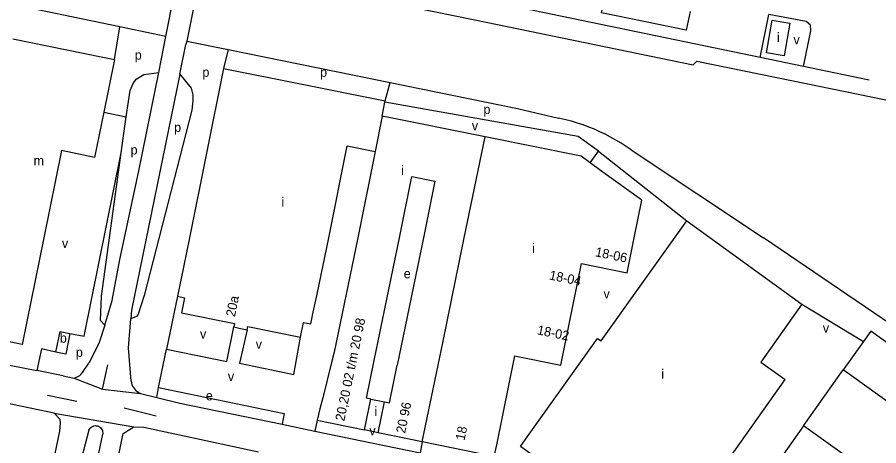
# Model space of a CAD drawing. Extents: x 157699 to 159683, y 381451 to 383293.
# Drawn here: x 158601.6 to 158968.6, y 382661.5 to 382844 of the extents above; entities that cross this region are included whole.
import ezdxf

# ---------------------------------------------------------------- set-up
doc = ezdxf.new("R2010")
doc.units = 0
for name, color, linetype in [('BLT_Basislijn', 7, 'Continuous'), ('BLT_Bebouwing', 7, 'Continuous'), ('BLT_Centroide', 7, 'Continuous'), ('BLT_Huisnummer', 7, 'Continuous'), ('BLT_Huisnummer_reeks', 7, 'Continuous'), ('BLT_Onderdoorgang_en_onderverdeling', 7, 'Continuous'), ('BLT_Onderverdeling_panden', 7, 'Continuous'), ('BLT_Vlakafsluiter', 7, 'Continuous')]:
    doc.layers.add(name, color=color, linetype=linetype)

msp = doc.modelspace()

# ---------------------------------------------------------------- linework, layer by layer
at = {"layer": 'BLT_Basislijn'}
for p, q in [((158645.35, 382839.82), (158432.83, 382884.22)), ((158664.82, 382835.75), (158669.66, 382859.56)), ((158678.92, 382859.01), (158673.76, 382833.82)), ((158918.11, 382826.83), (158801.5, 382851)), ((158918.11, 382826.83), (158921.71, 382845.17)), ((158642.99, 382826.01), (158645.35, 382839.82)), ((158664.82, 382835.75), (158645.35, 382839.82)), ((158661.89, 382820.42), (158664.82, 382835.75)), ((158670.79, 382819.7), (158673.45, 382832.31)), ((158673.76, 382833.82), (158673.45, 382832.31)), ((158673.76, 382833.82), (158691.37, 382830.23)), ((158691.37, 382830.23), (158689.49, 382822.2)), ((158691.37, 382830.23), (158760.4, 382816.15)), ((158936.46, 382823.03), (158918.11, 382826.83)), ((158964.55, 382817.2), (158936.46, 382823.03)), ((158931.34, 382817), (159045.89, 382793.42)), ((158758.28, 382808.34), (158760.4, 382816.15)), ((158760.4, 382816.15), (158814.72, 382805.07)), ((158638.43, 382803.49), (158648.01, 382801.54)), ((158814.72, 382805.07), (158832.18, 382801.03)), ((158863.07, 382787.52), (158919.5, 382750)), ((158845.69, 382781.94), (158849.21, 382786.88)), ((158849.21, 382786.88), (158886.76, 382757.21)), ((159006.18, 382690.97), (158919.5, 382750)), ((158669.87, 382725.15), (158665.12, 382702.55)), ((158935.87, 382721.83), (158962.04, 382705.95)), ((158661.71, 382686.31), (158665.12, 382702.55)), ((158572.04, 382700.92), (158609.92, 382693.48)), ((158629.33, 382692.66), (158632.12, 382696.59)), ((158637.94, 382685.58), (158640.17, 382695.97)), ((158621.08, 382691.29), (158609.92, 382693.48)), ((158936.51, 382669.95), (158953.34, 382693.76)), ((158621.08, 382691.29), (158625.78, 382690.28)), ((158661, 382682.04), (158661.71, 382686.31)), ((158661.71, 382686.31), (158715.33, 382675.27)), ((158614.53, 382682.98), (158626.98, 382680.42)), ((158654.09, 382683.73), (158661, 382682.04)), ((158661, 382682.04), (158670.81, 382679.61)), ((158647.2, 382677.69), (158660.73, 382674.19)), ((158670.81, 382679.61), (158714.38, 382670.62)), ((158715.33, 382675.27), (158714.38, 382670.62)), ((158714.38, 382670.62), (158728.37, 382667.73)), ((158729.33, 382672.39), (158728.37, 382667.73)), ((158632.1, 382668.1), (158627.93, 382652.23)), ((158633.77, 382645.88), (158637.98, 382666.43)), ((158728.37, 382667.73), (158773.15, 382658.49)), ((158774.11, 382663.19), (158773.15, 382658.49))]:
    msp.add_line(p, q, dxfattribs=at)
for points in [[(158691.76, 382856.98), (158703.62, 382861.92), (158796.54, 382842.79), (158889.46, 382823.66)], [(158936.46, 382823.03), (158939.58, 382838.18), (158939.46, 382840.58), (158937.71, 382842.17), (158921.71, 382845.17)], [(158889.46, 382823.66), (158891.12, 382825.28), (158931.34, 382817)], [(158638.85, 382712.9), (158641.95, 382723.32), (158645.33, 382740.8), (158653.29, 382777.78), (158661.89, 382820.42)], [(158648.01, 382801.54), (158649.74, 382812.74), (158650.95, 382815.7), (158652.28, 382817.61), (158655.46, 382819.65), (158661.89, 382820.42)], [(158670.79, 382819.7), (158650.24, 382719.16), (158650.02, 382715.51)], [(158670.79, 382819.7), (158675.67, 382813.69), (158676.35, 382810.95), (158676.45, 382808.55), (158675.89, 382804.34), (158655.59, 382725.53), (158653.1, 382717.46), (158652.36, 382716.46), (158650.02, 382715.51)], [(158849.21, 382786.88), (158840.48, 382793.13), (158758.18, 382807.85)], [(158645.87, 382786.28), (158647.57, 382798.64), (158648.01, 382801.54)], [(158863.07, 382787.52), (158860.96, 382788.97), (158858.8, 382790.36), (158856.6, 382791.68), (158854.36, 382792.93), (158852.08, 382794.11), (158849.76, 382795.22), (158847.42, 382796.26), (158845.04, 382797.22), (158842.63, 382798.11), (158840.2, 382798.92), (158837.74, 382799.66), (158835.26, 382800.32), (158832.76, 382800.9), (158832.18, 382801.03)], [(158624.04, 382709.35), (158630.09, 382708.12), (158645.87, 382786.28)], [(158638.85, 382712.9), (158637.08, 382714.79), (158637.48, 382725.25), (158645.87, 382786.28)], [(158650.13, 382688.93), (158649.02, 382703.17), (158650.02, 382715.51)], [(158638.85, 382712.9), (158636.37, 382705.03), (158632.12, 382696.59)], [(158665.12, 382702.55), (158690.86, 382697.39), (158693.84, 382712.06)], [(158699.53, 382710.91), (158696.28, 382696.59), (158719.38, 382691.77), (158722.29, 382707.72)], [(158618.08, 382701.4), (158611.98, 382702.8), (158609.92, 382693.48)], [(158625.78, 382690.28), (158627.18, 382690.8), (158627.73, 382691.09), (158628.25, 382691.45), (158628.71, 382691.87), (158629.12, 382692.35), (158629.33, 382692.66)], [(158617.29, 382675.37), (158540.03, 382691.39)], [(158650.13, 382688.93), (158650.26, 382688.23), (158650.46, 382687.55), (158650.73, 382686.89), (158651.08, 382686.27), (158651.49, 382685.69), (158651.97, 382685.16), (158652.5, 382684.69), (158653.09, 382684.28), (158654.09, 382683.73)], [(158609.02, 382616.76), (158619.67, 382667.64), (158619.98, 382671.21), (158619.82, 382672.73), (158617.29, 382675.37)], [(158627.78, 382574.46), (158646.65, 382666.74), (158651.26, 382669.61)], [(158632.1, 382668.1), (158632.32, 382668.55), (158632.61, 382668.95), (158632.96, 382669.3), (158633.36, 382669.59), (158633.8, 382669.82), (158634.27, 382669.97), (158634.76, 382670.04), (158635.26, 382670.03), (158635.74, 382669.94), (158636.21, 382669.77), (158636.65, 382669.53), (158637.04, 382669.23), (158637.37, 382668.86), (158637.64, 382668.45), (158637.85, 382668), (158637.97, 382667.52), (158638.02, 382667.03), (158637.99, 382666.54), (158637.98, 382666.43)], [(158651.26, 382669.61), (158655.48, 382669.36), (158704.29, 382658.95)]]:
    msp.add_lwpolyline(points, dxfattribs=at)
at = {"layer": 'BLT_Bebouwing'}
for p, q in [((158642.99, 382826.01), (158638.43, 382803.49)), ((158717.95, 382816.47), (158758.28, 382808.34)), ((158756.97, 382801.84), (158758.18, 382807.85)), ((158758.18, 382807.85), (158758.28, 382808.34)), ((158638.43, 382803.49), (158634.53, 382784.28)), ((158800.88, 382792.99), (158756.97, 382801.84)), ((158850.09, 382778.74), (158845.69, 382781.94)), ((158869.02, 382732.38), (158886.76, 382757.21)), ((158672.41, 382737.57), (158669.87, 382725.15)), ((158618.08, 382701.4), (158619.9, 382710.18)), ((158693.84, 382712.06), (158696.69, 382711.48)), ((158696.69, 382711.48), (158699.53, 382710.91)), ((158962.04, 382705.95), (158953.34, 382693.76)), ((158982, 382673.26), (158953.34, 382693.76)), ((158729.33, 382672.39), (158749.52, 382668.24)), ((158755.36, 382667.04), (158749.52, 382668.24)), ((158774.11, 382663.19), (158755.36, 382667.04)), ((158804.66, 382656.92), (158774.11, 382663.19))]:
    msp.add_line(p, q, dxfattribs=at)
for points in [[(158888.17, 382846.36), (158886.52, 382838.4), (158850.46, 382845.84), (158852.1, 382853.78), (158853.12, 382858.7)], [(158923.23, 382842.76), (158930.67, 382841.46), (158928.22, 382827.53), (158920.78, 382828.82), (158923.23, 382842.76)], [(158599.68, 382834.8), (158638.09, 382827.01), (158642.99, 382826.01)], [(158689.49, 382822.2), (158674.94, 382750), (158672.41, 382737.57)], [(158689.49, 382822.2), (158694.42, 382821.21), (158717.95, 382816.47)], [(158845.69, 382781.94), (158841.84, 382784.74), (158800.88, 382792.99)], [(158634.53, 382784.28), (158620.4, 382787.15), (158612.86, 382750), (158603.62, 382704.58), (158574.14, 382710.64)], [(158729.28, 382725.97), (158734.26, 382749.98), (158742.15, 382789.16), (158754.08, 382786.76)], [(158754.08, 382786.76), (158746.66, 382749.98), (158736.58, 382701.36)], [(158753.63, 382697.84), (158764.41, 382749.99), (158769.68, 382776.13), (158779.52, 382774.14), (158774.66, 382749.99), (158763.48, 382695.81)], [(158841.95, 382739.07), (158861.34, 382735.09), (158864.4, 382750), (158867.62, 382766), (158850.09, 382778.74)], [(158886.76, 382757.21), (158935.87, 382721.83)], [(158813.46, 382699.81), (158833.07, 382695.79), (158841.95, 382739.07)], [(158822.5, 382670.34), (158848.8, 382707.22), (158850.29, 382706.16), (158869.02, 382732.38)], [(158669.87, 382725.15), (158672.9, 382724.53), (158671.61, 382718.14), (158694.15, 382713.57), (158693.84, 382712.06)], [(158722.29, 382707.72), (158723.57, 382714.04), (158726.68, 382713.41), (158727.7, 382718.31), (158729.28, 382725.97)], [(158935.87, 382721.83), (158918.27, 382697.09), (158928.69, 382689.69)], [(158619.9, 382710.18), (158624.04, 382709.35)], [(158699.53, 382710.91), (158699.81, 382712.27), (158722.29, 382707.72)], [(159002.59, 382676.93), (159000.04, 382678.78), (158986.47, 382688.48), (158989.52, 382692.77), (158965.21, 382710.22), (158962.04, 382705.95)], [(158624.04, 382709.35), (158622.24, 382700.54), (158618.08, 382701.4)], [(158736.58, 382701.36), (158735.61, 382697.47), (158731.69, 382681.82), (158730.55, 382677.24), (158729.33, 382672.39)], [(158813.46, 382699.81), (158805.67, 382661.82), (158804.66, 382656.92)], [(158752.2, 382681.33), (158750.3, 382681.72), (158753.63, 382697.84)], [(158758.05, 382680.15), (158760.16, 382679.72), (158763.48, 382695.81)], [(158866.32, 382644.97), (158886.74, 382630.33), (158928.69, 382689.69)], [(158752.2, 382681.33), (158758.05, 382680.15)], [(158821.57, 382657.09), (158815.94, 382661.1), (158818.99, 382665.41), (158822.5, 382670.34)], [(158936.51, 382669.95), (158924.53, 382653.05)], [(158960.51, 382652.79), (158936.51, 382669.95)]]:
    msp.add_lwpolyline(points, dxfattribs=at)
at = {"layer": 'BLT_Onderdoorgang_en_onderverdeling'}
for points in [[(158749.52, 382668.24), (158752.2, 382681.33)], [(158755.36, 382667.04), (158758.05, 382680.15)]]:
    msp.add_lwpolyline(points, dxfattribs=at)
at = {"layer": 'BLT_Onderverdeling_panden'}
for p, q in [((158756.97, 382801.84), (158754.08, 382786.76)), ((158791.88, 382749.35), (158800.88, 382792.99)), ((158782.96, 382706.07), (158791.88, 382749.35)), ((158780.13, 382692.38), (158782.96, 382706.07)), ((158774.11, 382663.19), (158780.13, 382692.38))]:
    msp.add_line(p, q, dxfattribs=at)
at = {"layer": 'BLT_Vlakafsluiter'}
for p, q in [((158625.78, 382690.28), (158637.94, 382685.58)), ((158637.94, 382685.58), (158654.09, 382683.73)), ((158617.29, 382675.37), (158651.26, 382669.61))]:
    msp.add_line(p, q, dxfattribs=at)

# ---------------------------------------------------------------- texts
at = {"layer": 'BLT_Centroide'}
for s, p in [('i', (158925.19, 382833.41)), ('v', (158932.23, 382832.42)), ('p', (158651.63, 382825.92)), ('p', (158680.47, 382818.6)), ('p', (158730.6, 382818.6)), ('p', (158800.19, 382802.76)), ('p', (158668.43, 382795.13)), ('v', (158795.24, 382795.83)), ('p', (158649.86, 382785.54)), ('m', (158608.56, 382780.94)), ('i', (158765.11, 382776.81)), ('i', (158714.08, 382763.31)), ('v', (158620.62, 382745.76)), ('i', (158820.86, 382743.62)), ('e', (158766.22, 382732.81)), ('v', (158851.31, 382724.23)), ('v', (158679.45, 382707.15)), ('v', (158944.73, 382709.64)), ('b', (158619.73, 382705.36)), ('v', (158703.17, 382702.78)), ('p', (158626.56, 382699.34)), ('v', (158691.31, 382689.04)), ('i', (158875.91, 382690.06)), ('e', (158681.92, 382680.82)), ('i', (158753.78, 382674.19)), ('v', (158751.57, 382665.96))]:
    msp.add_text(s, height=4, dxfattribs=at).set_placement(p)
at = {"layer": 'BLT_Huisnummer'}
msp.add_text('20a', height=4, rotation=78.2936, dxfattribs=at).set_placement((158694.29, 382716.16))
at = {"layer": 'BLT_Huisnummer_reeks'}
for s, rotation, p in [('18-06', 348.4011, (158847.56, 382742.21)), ('18-04', 348.4011, (158827.98, 382732.34)), ('20,20 02 t/m 20 98', 78.3458, (158740.88, 382671.75)), ('18-02', 348.3992, (158822.79, 382708.98)), ('20 96', 78.3458, (158766.78, 382666.51)), ('18', 78.4018, (158792.1, 382663.51))]:
    msp.add_text(s, height=4, rotation=rotation, dxfattribs=at).set_placement(p)

doc.saveas('drawing.dxf')
